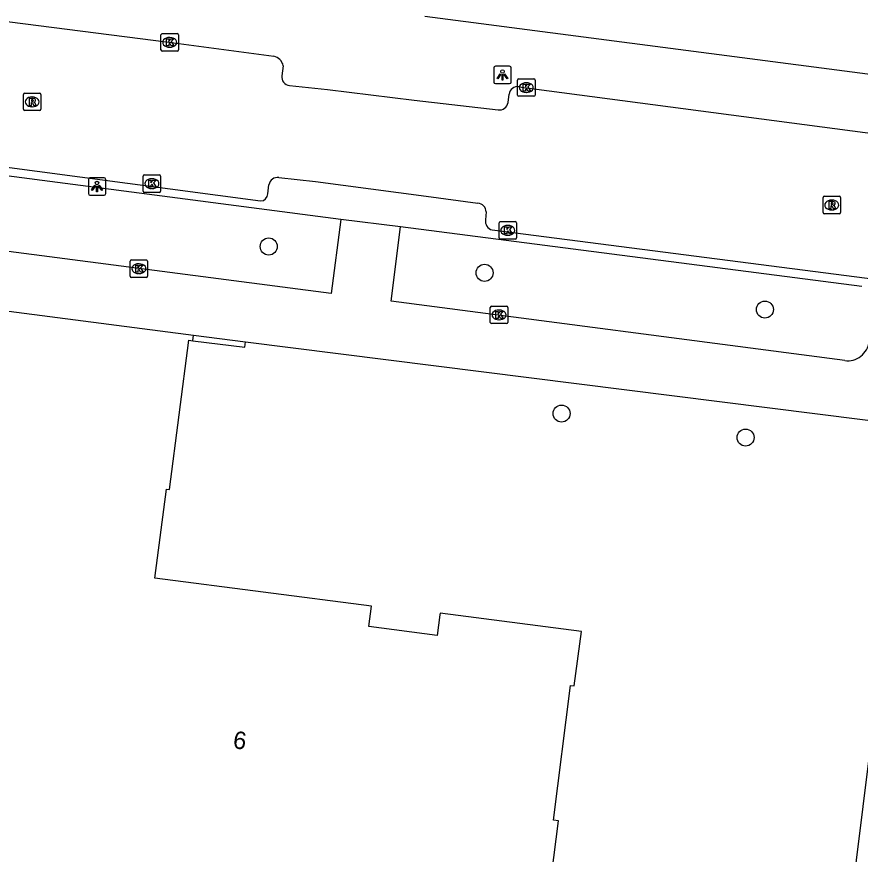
# Model space of a CAD drawing. Extents: x 162186 to 163152, y 385513 to 386513.
# Drawn here: x 162322.01 to 162370.33, y 386098.95 to 386146.91 of the extents above; entities that cross this region are included whole.
import ezdxf

# ---------------------------------------------------------------- set-up
doc = ezdxf.new("R2010")
doc.units = 0
for name, color, linetype in [('IMGEO_Boom', 7, 'Continuous'), ('IMGEO_Groenvoorziening', 7, 'Continuous'), ('IMGEO_Kolk', 7, 'Continuous'), ('IMGEO_Lichtpunt', 7, 'Continuous'), ('IMGEO_Muur', 7, 'Continuous'), ('IMGEO_Pand', 7, 'Continuous'), ('IMGEO_Pand_nummerreeks', 7, 'Continuous'), ('IMGEO_Rijbaan_lokaal_gesloten', 7, 'Continuous'), ('IMGEO_Rioolput', 7, 'Continuous'), ('IMGEO_Voetpad_open', 7, 'Continuous')]:
    doc.layers.add(name, color=color, linetype=linetype)

msp = doc.modelspace()

# ---------------------------------------------------------------- linework, layer by layer
at = {"layer": 'IMGEO_Boom'}
for centre in [(162336.44, 386133.757), (162348.811, 386132.249), (162364.874, 386130.145), (162353.222, 386124.188), (162363.766, 386122.813)]:
    msp.add_circle(centre, 0.489, dxfattribs=at)
at = {"layer": 'IMGEO_Groenvoorziening'}
msp.add_lwpolyline([(162373.204, 386123.496), (162366.618, 386070.643)], dxfattribs=at)
at = {"layer": 'IMGEO_Kolk'}
for p, q in [((162330.267, 386145.023), (162330.267, 386145.875)), ((162330.342, 386145.949), (162331.194, 386145.949)), ((162330.755, 386145.729), (162330.78, 386145.729)), ((162331.268, 386145.875), (162331.268, 386145.023)), ((162331.194, 386144.949), (162330.342, 386144.949)), ((162330.778, 386145.169), (162330.753, 386145.169)), ((162350.702, 386142.434), (162350.702, 386143.286)), ((162350.777, 386143.36), (162351.629, 386143.36)), ((162351.703, 386143.286), (162351.703, 386142.434)), ((162351.19, 386143.14), (162351.215, 386143.14)), ((162351.629, 386142.36), (162350.777, 386142.36)), ((162351.213, 386142.58), (162351.188, 386142.58)), ((162329.248, 386136.93), (162329.248, 386137.782)), ((162329.323, 386137.856), (162330.175, 386137.856)), ((162329.736, 386137.636), (162329.761, 386137.636)), ((162330.249, 386137.782), (162330.249, 386136.93)), ((162329.759, 386137.076), (162329.734, 386137.076)), ((162330.175, 386136.856), (162329.323, 386136.856)), ((162349.638, 386134.256), (162349.638, 386135.108)), ((162349.713, 386135.182), (162350.565, 386135.182)), ((162350.639, 386135.108), (162350.639, 386134.256)), ((162350.126, 386134.962), (162350.151, 386134.962)), ((162350.565, 386134.182), (162349.713, 386134.182)), ((162350.149, 386134.402), (162350.124, 386134.402)), ((162328.503, 386132.059), (162328.503, 386132.911)), ((162328.578, 386132.985), (162329.43, 386132.985)), ((162328.991, 386132.765), (162329.016, 386132.765)), ((162329.504, 386132.911), (162329.504, 386132.059)), ((162329.014, 386132.205), (162328.989, 386132.205)), ((162329.43, 386131.985), (162328.578, 386131.985)), ((162349.138, 386129.413), (162349.138, 386130.265)), ((162349.213, 386130.339), (162350.065, 386130.339)), ((162350.139, 386130.265), (162350.139, 386129.413)), ((162349.626, 386130.119), (162349.651, 386130.119)), ((162350.065, 386129.339), (162349.213, 386129.339)), ((162349.649, 386129.559), (162349.624, 386129.559))]:
    msp.add_line(p, q, dxfattribs=at)
for points in [[(162330.267, 386145.023), (162330.267, 386145.875)], [(162330.342, 386145.949), (162331.194, 386145.949)], [(162331.268, 386145.875), (162331.268, 386145.023)], [(162330.588, 386145.649), (162330.711, 386145.649), (162330.711, 386145.498), (162330.841, 386145.649), (162331.005, 386145.649), (162330.859, 386145.498), (162331.012, 386145.249), (162330.86, 386145.249), (162330.775, 386145.413), (162330.711, 386145.346), (162330.711, 386145.249), (162330.588, 386145.249), (162330.588, 386145.649)], [(162331.194, 386144.949), (162330.342, 386144.949)], [(162350.702, 386142.434), (162350.702, 386143.286)], [(162350.777, 386143.36), (162351.629, 386143.36)], [(162351.703, 386143.286), (162351.703, 386142.434)], [(162351.023, 386143.06), (162351.146, 386143.06), (162351.146, 386142.909), (162351.276, 386143.06), (162351.44, 386143.06), (162351.294, 386142.909), (162351.447, 386142.66), (162351.295, 386142.66), (162351.21, 386142.824), (162351.146, 386142.757), (162351.146, 386142.66), (162351.023, 386142.66), (162351.023, 386143.06)], [(162351.629, 386142.36), (162350.777, 386142.36)], [(162329.248, 386136.93), (162329.248, 386137.782)], [(162329.323, 386137.856), (162330.175, 386137.856)], [(162329.569, 386137.556), (162329.692, 386137.556), (162329.692, 386137.405), (162329.822, 386137.556), (162329.986, 386137.556), (162329.84, 386137.405), (162329.993, 386137.156), (162329.841, 386137.156), (162329.756, 386137.32), (162329.692, 386137.253), (162329.692, 386137.156), (162329.569, 386137.156), (162329.569, 386137.556)], [(162330.249, 386137.782), (162330.249, 386136.93)], [(162330.175, 386136.856), (162329.323, 386136.856)], [(162349.638, 386134.256), (162349.638, 386135.108)], [(162349.713, 386135.182), (162350.565, 386135.182)], [(162350.639, 386135.108), (162350.639, 386134.256)], [(162349.959, 386134.882), (162350.082, 386134.882), (162350.082, 386134.731), (162350.212, 386134.882), (162350.376, 386134.882), (162350.23, 386134.731), (162350.383, 386134.482), (162350.231, 386134.482), (162350.146, 386134.646), (162350.082, 386134.579), (162350.082, 386134.482), (162349.959, 386134.482), (162349.959, 386134.882)], [(162350.565, 386134.182), (162349.713, 386134.182)], [(162328.503, 386132.059), (162328.503, 386132.911)], [(162328.578, 386132.985), (162329.43, 386132.985)], [(162328.824, 386132.685), (162328.947, 386132.685), (162328.947, 386132.534), (162329.077, 386132.685), (162329.241, 386132.685), (162329.095, 386132.534), (162329.248, 386132.285), (162329.096, 386132.285), (162329.011, 386132.449), (162328.947, 386132.382), (162328.947, 386132.285), (162328.824, 386132.285), (162328.824, 386132.685)], [(162329.504, 386132.911), (162329.504, 386132.059)], [(162329.43, 386131.985), (162328.578, 386131.985)], [(162349.138, 386129.413), (162349.138, 386130.265)], [(162349.213, 386130.339), (162350.065, 386130.339)], [(162350.139, 386130.265), (162350.139, 386129.413)], [(162349.459, 386130.039), (162349.582, 386130.039), (162349.582, 386129.888), (162349.712, 386130.039), (162349.876, 386130.039), (162349.73, 386129.888), (162349.883, 386129.639), (162349.731, 386129.639), (162349.646, 386129.803), (162349.582, 386129.736), (162349.582, 386129.639), (162349.459, 386129.639), (162349.459, 386130.039)], [(162350.065, 386129.339), (162349.213, 386129.339)]]:
    msp.add_lwpolyline(points, dxfattribs=at)
for centre, start, end in [((162330.344, 386145.873), 91.552, 178.448), ((162330.344, 386145.873), 91.552, 178.448), ((162331.192, 386145.873), 1.552, 88.448), ((162331.192, 386145.873), 1.552, 88.448), ((162330.344, 386145.025), 181.552, 268.448), ((162330.344, 386145.025), 181.552, 268.448), ((162331.192, 386145.025), 271.552, 358.448), ((162331.192, 386145.025), 271.552, 358.448), ((162350.779, 386143.284), 91.552, 178.448), ((162350.779, 386143.284), 91.552, 178.448), ((162351.627, 386143.284), 1.552, 88.448), ((162351.627, 386143.284), 1.552, 88.448), ((162350.779, 386142.436), 181.552, 268.448), ((162350.779, 386142.436), 181.552, 268.448), ((162351.627, 386142.436), 271.552, 358.448), ((162351.627, 386142.436), 271.552, 358.448), ((162329.325, 386137.78), 91.552, 178.448), ((162329.325, 386137.78), 91.552, 178.448), ((162330.173, 386137.78), 1.552, 88.448), ((162330.173, 386137.78), 1.552, 88.448), ((162329.325, 386136.932), 181.552, 268.448), ((162329.325, 386136.932), 181.552, 268.448), ((162330.173, 386136.932), 271.552, 358.448), ((162330.173, 386136.932), 271.552, 358.448), ((162349.715, 386135.106), 91.552, 178.448), ((162349.715, 386135.106), 91.552, 178.448), ((162350.563, 386135.106), 1.552, 88.448), ((162350.563, 386135.106), 1.552, 88.448), ((162349.715, 386134.258), 181.552, 268.448), ((162349.715, 386134.258), 181.552, 268.448), ((162350.563, 386134.258), 271.552, 358.448), ((162350.563, 386134.258), 271.552, 358.448), ((162328.58, 386132.909), 91.552, 178.448), ((162328.58, 386132.909), 91.552, 178.448), ((162329.428, 386132.909), 1.552, 88.448), ((162329.428, 386132.909), 1.552, 88.448), ((162328.58, 386132.061), 181.552, 268.448), ((162328.58, 386132.061), 181.552, 268.448), ((162329.428, 386132.061), 271.552, 358.448), ((162329.428, 386132.061), 271.552, 358.448), ((162349.215, 386130.263), 91.552, 178.448), ((162349.215, 386130.263), 91.552, 178.448), ((162350.063, 386130.263), 1.552, 88.448), ((162350.063, 386130.263), 1.552, 88.448), ((162349.215, 386129.415), 181.552, 268.448), ((162349.215, 386129.415), 181.552, 268.448), ((162350.063, 386129.415), 271.552, 358.448), ((162350.063, 386129.415), 271.552, 358.448)]:
    msp.add_arc(centre, 0.0765, start, end, dxfattribs=at)
for centre, major_axis, ratio, start_param, end_param in [((162330.754, 386145.449), (-0.387, 0.002), 0.722429, 4.712389, 7.853982), ((162330.779, 386145.449), (-0.39, 0.002), 0.717154, 1.570796, 4.712389), ((162351.189, 386142.86), (-0.387, 0.002), 0.722429, 4.712389, 7.853982), ((162351.214, 386142.86), (-0.39, 0.002), 0.717154, 1.570796, 4.712389), ((162329.735, 386137.356), (-0.387, 0.002), 0.722429, 4.712389, 7.853982), ((162329.76, 386137.356), (-0.39, 0.002), 0.717154, 1.570796, 4.712389), ((162350.125, 386134.682), (-0.387, 0.002), 0.722429, 4.712389, 7.853982), ((162350.15, 386134.682), (-0.39, 0.002), 0.717154, 1.570796, 4.712389), ((162328.99, 386132.485), (-0.387, 0.002), 0.722429, 4.712389, 7.853982), ((162329.015, 386132.485), (-0.39, 0.002), 0.717154, 1.570796, 4.712389), ((162349.625, 386129.839), (-0.387, 0.002), 0.722429, 4.712389, 7.853982), ((162349.65, 386129.839), (-0.39, 0.002), 0.717154, 1.570796, 4.712389)]:
    msp.add_ellipse(centre, major_axis=major_axis, ratio=ratio, start_param=start_param, end_param=end_param, dxfattribs=at)
at = {"layer": 'IMGEO_Lichtpunt'}
for p, q in [((162349.337, 386143.986), (162349.337, 386143.179)), ((162349.337, 386143.986), (162349.337, 386143.179)), ((162350.239, 386144.081), (162349.431, 386144.081)), ((162350.239, 386144.081), (162349.431, 386144.081)), ((162350.333, 386143.179), (162350.333, 386143.986)), ((162350.333, 386143.179), (162350.333, 386143.986)), ((162349.431, 386143.085), (162350.239, 386143.085)), ((162349.431, 386143.085), (162350.239, 386143.085)), ((162326.106, 386137.598), (162326.106, 386136.791)), ((162326.106, 386137.598), (162326.106, 386136.791)), ((162327.008, 386137.693), (162326.2, 386137.693)), ((162327.008, 386137.693), (162326.2, 386137.693)), ((162327.102, 386136.791), (162327.102, 386137.598)), ((162327.102, 386136.791), (162327.102, 386137.598)), ((162326.2, 386136.697), (162327.008, 386136.697)), ((162326.2, 386136.697), (162327.008, 386136.697))]:
    msp.add_line(p, q, dxfattribs=at)
for points in [[(162349.711, 386143.65), (162349.75, 386143.622), (162349.562, 386143.36), (162349.524, 386143.387), (162349.711, 386143.65)], [(162349.813, 386143.602), (162349.86, 386143.602), (162349.86, 386143.28), (162349.813, 386143.28), (162349.813, 386143.602)], [(162349.923, 386143.622), (162349.961, 386143.649), (162350.148, 386143.387), (162350.109, 386143.359), (162349.923, 386143.622)], [(162326.48, 386137.262), (162326.519, 386137.234), (162326.331, 386136.972), (162326.293, 386136.999), (162326.48, 386137.262)], [(162326.582, 386137.214), (162326.629, 386137.214), (162326.629, 386136.892), (162326.582, 386136.892), (162326.582, 386137.214)], [(162326.692, 386137.234), (162326.73, 386137.261), (162326.917, 386136.999), (162326.878, 386136.971), (162326.692, 386137.234)]]:
    msp.add_lwpolyline(points, dxfattribs=at)
for centre in [(162349.836, 386143.784), (162326.605, 386137.396)]:
    msp.add_circle(centre, 0.0994, dxfattribs=at)
for centre, start, end in [((162349.431, 386143.986), 90, 180), ((162349.431, 386143.986), 90, 180), ((162350.239, 386143.986), 0, 90), ((162350.239, 386143.986), 0, 90), ((162349.431, 386143.179), 180, 270), ((162349.431, 386143.179), 180, 270), ((162350.239, 386143.179), 270, 0), ((162350.239, 386143.179), 270, 360), ((162326.2, 386137.598), 90, 180), ((162326.2, 386137.598), 90, 180), ((162327.008, 386137.598), 0, 90), ((162327.008, 386137.598), 0, 90), ((162326.2, 386136.791), 180, 270), ((162326.2, 386136.791), 180, 270), ((162327.008, 386136.791), 270, 0), ((162327.008, 386136.791), 270, 360)]:
    msp.add_arc(centre, 0.0946, start, end, dxfattribs=at)
at = {"layer": 'IMGEO_Muur'}
for points in [[(162332.087, 386128.361), (162335.068, 386127.985), (162335.109, 386128.306)], [(162332.132, 386128.681), (162335.109, 386128.306)]]:
    msp.add_lwpolyline(points, dxfattribs=at)
at = {"layer": 'IMGEO_Pand'}
for points in [[(162319.033, 386130.38), (162332.132, 386128.681)], [(162352.645, 386097.705), (162353.044, 386100.856), (162352.753, 386100.893), (162353.731, 386108.618), (162353.951, 386108.591), (162354.356, 386111.715), (162346.268, 386112.763), (162346.254, 386112.656), (162346.102, 386111.474), (162342.175, 386111.983), (162342.327, 386113.162), (162329.919, 386114.762), (162330.577, 386119.86), (162330.765, 386119.836), (162331.871, 386128.389), (162332.087, 386128.361)], [(162332.087, 386128.361), (162332.132, 386128.681)]]:
    msp.add_lwpolyline(points, dxfattribs=at)
at = {"layer": 'IMGEO_Rijbaan_lokaal_gesloten'}
for points in [[(162261.989, 386154.265), (162271.357, 386153.064), (162275.732, 386152.503), (162330.715, 386145.455), (162336.73, 386144.652)], [(162337.265, 386144.111), (162337.192, 386143.537)], [(162337.639, 386142.983), (162339.801, 386142.756), (162344.778, 386142.132), (162349.591, 386141.579)], [(162350.777, 386142.911), (162387.999, 386137.992)], [(162350.153, 386142.011), (162350.215, 386142.481)], [(162310.353, 386139.77), (162335.977, 386136.365)], [(162337.015, 386137.713), (162339.131, 386137.472), (162345.458, 386136.636), (162348.427, 386136.243)], [(162336.388, 386136.776), (162336.457, 386137.295)], [(162348.904, 386135.735), (162348.861, 386135.293)], [(162349.248, 386134.706), (162413.706, 386126.402)]]:
    msp.add_lwpolyline(points, dxfattribs=at)
for centre, radius, start, end in [((162336.618, 386144.006), 0.656, 9.222, 80.139), ((162337.674, 386143.469), 0.487, 171.9173, 265.88), ((162350.712, 386142.414), 0.501, 82.5164, 172.3246), ((162349.652, 386142.081), 0.506, 263.1022, 351.9955), ((162336.965, 386137.199), 0.517, 84.4289, 169.2452), ((162335.965, 386136.788), 0.423, 271.612, 358.388), ((162348.366, 386135.708), 0.539, 2.898, 83.4968), ((162349.387, 386135.218), 0.531, 171.9307, 254.8618)]:
    msp.add_arc(centre, radius, start, end, dxfattribs=at)
at = {"layer": 'IMGEO_Rioolput'}
for p, q in [((162322.385, 386141.615), (162322.385, 386142.467)), ((162322.46, 386142.541), (162323.312, 386142.541)), ((162322.873, 386142.321), (162322.898, 386142.321)), ((162323.386, 386142.467), (162323.386, 386141.615)), ((162323.312, 386141.541), (162322.46, 386141.541)), ((162322.896, 386141.761), (162322.871, 386141.761)), ((162368.204, 386135.708), (162368.204, 386136.56)), ((162368.279, 386136.634), (162369.131, 386136.634)), ((162369.205, 386136.56), (162369.205, 386135.708)), ((162368.692, 386136.414), (162368.717, 386136.414)), ((162369.131, 386135.634), (162368.279, 386135.634)), ((162368.715, 386135.854), (162368.69, 386135.854))]:
    msp.add_line(p, q, dxfattribs=at)
for points in [[(162322.385, 386141.615), (162322.385, 386142.467)], [(162322.46, 386142.541), (162323.312, 386142.541)], [(162323.386, 386142.467), (162323.386, 386141.615)], [(162322.974, 386142.239), (162322.722, 386142.241), (162322.722, 386141.841)], [(162322.722, 386141.841), (162322.846, 386141.841), (162322.846, 386142.003), (162322.857, 386142.003)], [(162322.9, 386142.16), (162322.846, 386142.16), (162322.846, 386142.079)], [(162322.846, 386142.079), (162322.898, 386142.079)], [(162322.904, 386141.974), (162322.975, 386141.841), (162323.115, 386141.841), (162323.05, 386141.967)], [(162323.312, 386141.541), (162322.46, 386141.541)], [(162368.204, 386135.708), (162368.204, 386136.56)], [(162368.279, 386136.634), (162369.131, 386136.634)], [(162369.205, 386136.56), (162369.205, 386135.708)], [(162368.793, 386136.332), (162368.541, 386136.334), (162368.541, 386135.934)], [(162368.541, 386135.934), (162368.665, 386135.934), (162368.665, 386136.096), (162368.676, 386136.096)], [(162368.719, 386136.253), (162368.665, 386136.253), (162368.665, 386136.172)], [(162368.665, 386136.172), (162368.717, 386136.172)], [(162368.723, 386136.067), (162368.794, 386135.934), (162368.934, 386135.934), (162368.869, 386136.06)], [(162369.131, 386135.634), (162368.279, 386135.634)]]:
    msp.add_lwpolyline(points, dxfattribs=at)
for centre, radius, start, end in [((162322.462, 386142.465), 0.0765, 91.552, 178.448), ((162322.462, 386142.465), 0.0765, 91.552, 178.448), ((162323.31, 386142.465), 0.0765, 1.552, 88.448), ((162323.31, 386142.465), 0.0765, 1.552, 88.448), ((162322.856, 386141.95), 0.0533, 26.0293, 88.6989), ((162322.882, 386142.268), 0.19, 274.7715, 282.9687), ((162322.906, 386142.064), 0.0964, 77.0061, 93.1865), ((162322.92, 386142.121), 0.0378, 276.6634, 79.6772), ((162322.973, 386142.129), 0.109, 350.3612, 89.416), ((162322.971, 386142.129), 0.112, 277.5842, 350.9817), ((162322.955, 386141.914), 0.108, 29.5134, 73.7905), ((162322.462, 386141.617), 0.0765, 181.552, 268.448), ((162322.462, 386141.617), 0.0765, 181.552, 268.448), ((162323.31, 386141.617), 0.0765, 271.552, 358.448), ((162323.31, 386141.617), 0.0765, 271.552, 358.448), ((162368.281, 386136.558), 0.0765, 91.552, 178.448), ((162368.281, 386136.558), 0.0765, 91.552, 178.448), ((162369.129, 386136.558), 0.0765, 1.552, 88.448), ((162369.129, 386136.558), 0.0765, 1.552, 88.448), ((162368.675, 386136.043), 0.0533, 26.0293, 88.6989), ((162368.701, 386136.361), 0.19, 274.7715, 282.9687), ((162368.725, 386136.157), 0.0964, 77.0061, 93.1865), ((162368.739, 386136.214), 0.0378, 276.6634, 79.6772), ((162368.792, 386136.222), 0.109, 350.3612, 89.416), ((162368.79, 386136.222), 0.112, 277.5842, 350.9817), ((162368.774, 386136.007), 0.108, 29.5134, 73.7905), ((162368.281, 386135.71), 0.0765, 181.552, 268.448), ((162368.281, 386135.71), 0.0765, 181.552, 268.448), ((162369.129, 386135.71), 0.0765, 271.552, 358.448), ((162369.129, 386135.71), 0.0765, 271.552, 358.448)]:
    msp.add_arc(centre, radius, start, end, dxfattribs=at)
for centre, major_axis, ratio, start_param, end_param in [((162322.872, 386142.041), (-0.387, 0.002), 0.722429, 4.712389, 7.853982), ((162322.897, 386142.041), (-0.39, 0.002), 0.717154, 1.570796, 4.712389), ((162368.691, 386136.134), (-0.387, 0.002), 0.722429, 4.712389, 7.853982), ((162368.716, 386136.134), (-0.39, 0.002), 0.717154, 1.570796, 4.712389)]:
    msp.add_ellipse(centre, major_axis=major_axis, ratio=ratio, start_param=start_param, end_param=end_param, dxfattribs=at)
at = {"layer": 'IMGEO_Voetpad_open'}
for points in [[(162477.513, 386129.721), (162345.395, 386146.93)], [(162340.574, 386135.313), (162310.282, 386139.248)], [(162340.574, 386135.313), (162340.025, 386131.074), (162309.042, 386135.089)], [(162343.99, 386134.88), (162340.574, 386135.313)], [(162369.451, 386127.225), (162343.455, 386130.63), (162343.99, 386134.88)], [(162370.427, 386131.472), (162343.99, 386134.88)], [(162335.109, 386128.306), (162373.204, 386123.496)]]:
    msp.add_lwpolyline(points, dxfattribs=at)
msp.add_arc((162369.615, 386128.454), 1.24, 262.4197, 352.6896, dxfattribs=at)

# ---------------------------------------------------------------- texts
at = {"layer": 'IMGEO_Pand_nummerreeks'}
msp.add_text('6', height=1, rotation=352.6252, dxfattribs=at).set_placement((162334.357, 386105.026))

doc.saveas('drawing.dxf')
